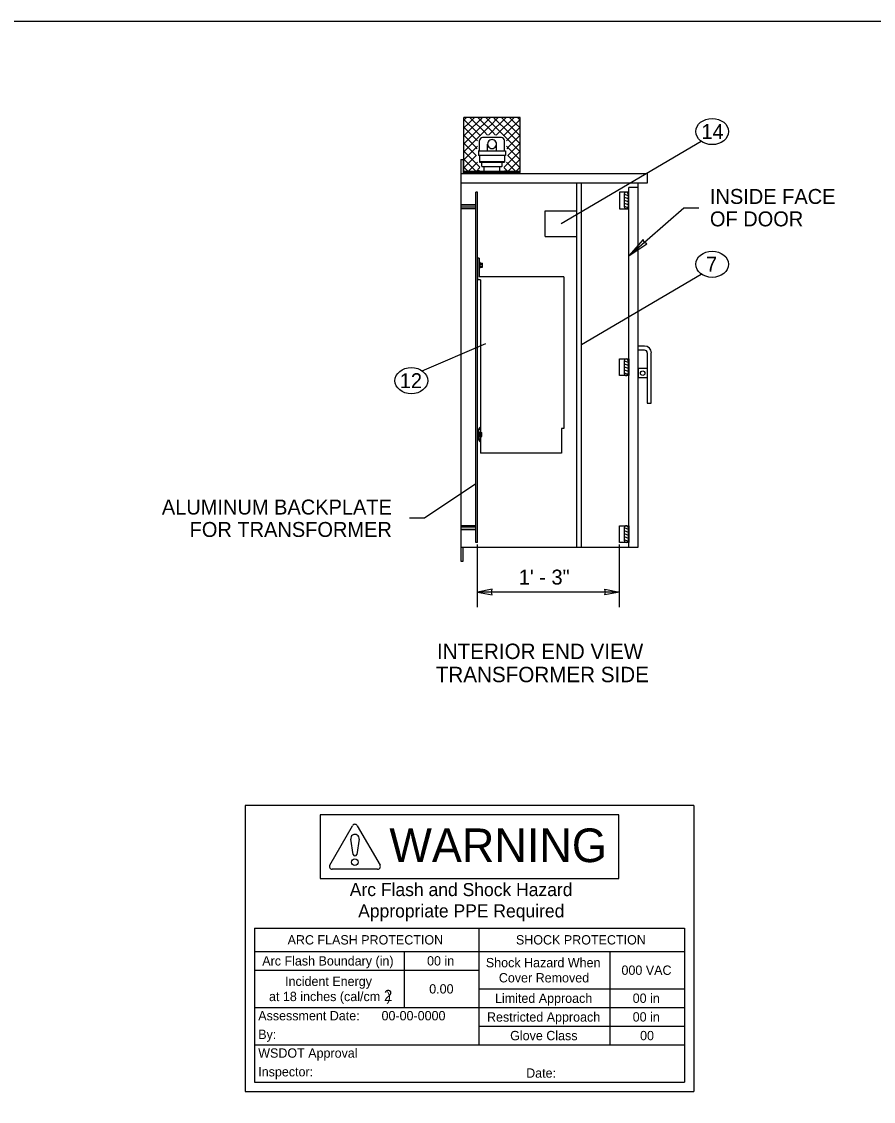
# Model space of a CAD drawing. Extents: x 99862 to 103680, y 99470 to 105076.
# Drawn here: x 100773 to 101684, y 103920 to 105076 of the extents above; entities that cross this region are included whole.
import ezdxf

# ---------------------------------------------------------------- set-up
doc = ezdxf.new("R2010")
doc.units = 0
for name, color, linetype in [('Level 1', 7, 'Continuous'), ('Level 15', 7, 'Continuous'), ('Level 20', 7, 'Continuous'), ('Level 35', 7, 'Continuous'), ('Level 40', 7, 'Continuous')]:
    doc.layers.add(name, color=color, linetype=linetype)

msp = doc.modelspace()

# ---------------------------------------------------------------- linework, layer by layer
at = {"layer": 'Level 1'}
for p, q in [((101246.5, 104915.2), (101246.5, 104972.9)), ((101306.5, 104972.9), (101246.5, 104972.9)), ((101246.5, 104970.7), (101246.7, 104970.5)), ((101246.7, 104970.5), (101246.5, 104970.3)), ((101246.5, 104962.2), (101246.7, 104962)), ((101246.7, 104970.5), (101249.1, 104972.9)), ((101250.9, 104966.2), (101246.7, 104970.5)), ((101246.7, 104962), (101250.9, 104966.2)), ((101255.2, 104970.5), (101250.9, 104966.2)), ((101250.9, 104966.2), (101255.2, 104962)), ((101252.7, 104972.9), (101255.2, 104970.5)), ((101257.6, 104972.9), (101255.2, 104970.5)), ((101255.2, 104970.5), (101259.4, 104966.2)), ((101259.4, 104966.2), (101255.2, 104962)), ((101259.4, 104966.2), (101263.7, 104970.5)), ((101263.7, 104962), (101259.4, 104966.2)), ((101263.7, 104970.5), (101261.2, 104972.9)), ((101266.1, 104972.9), (101263.7, 104970.5)), ((101263.7, 104970.5), (101268, 104966.2)), ((101268, 104966.2), (101263.7, 104962)), ((101268, 104966.2), (101272.2, 104970.5)), ((101272.2, 104962), (101268, 104966.2)), ((101272.2, 104970.5), (101269.8, 104972.9)), ((101274.7, 104972.9), (101272.2, 104970.5)), ((101272.2, 104970.5), (101276.5, 104966.2)), ((101276.5, 104966.2), (101272.2, 104962)), ((101276.5, 104966.2), (101280.7, 104970.5)), ((101280.7, 104962), (101276.5, 104966.2)), ((101280.7, 104970.5), (101278.3, 104972.9)), ((101283.2, 104972.9), (101280.7, 104970.5)), ((101280.7, 104970.5), (101285, 104966.2)), ((101285, 104966.2), (101280.7, 104962)), ((101285, 104966.2), (101289.2, 104970.5)), ((101289.2, 104962), (101285, 104966.2)), ((101289.2, 104970.5), (101286.8, 104972.9)), ((101291.7, 104972.9), (101289.2, 104970.5)), ((101289.2, 104970.5), (101293.5, 104966.2)), ((101293.5, 104966.2), (101289.2, 104962)), ((101293.5, 104966.2), (101297.7, 104970.5)), ((101297.7, 104962), (101293.5, 104966.2)), ((101295.3, 104972.9), (101297.7, 104970.5)), ((101297.7, 104970.5), (101300.2, 104972.9)), ((101297.7, 104970.5), (101302, 104966.2)), ((101302, 104966.2), (101297.7, 104962)), ((101302, 104966.2), (101306.2, 104970.5)), ((101306.2, 104962), (101302, 104966.2)), ((101306.2, 104970.5), (101303.8, 104972.9)), ((101306.5, 104970.7), (101306.2, 104970.5)), ((101306.2, 104970.5), (101306.5, 104970.3)), ((101306.5, 104962.2), (101306.2, 104962)), ((101306.5, 104915.2), (101306.5, 104972.9)), ((101246.7, 104962), (101246.5, 104961.8)), ((101246.5, 104953.7), (101246.7, 104953.5)), ((101246.7, 104953.5), (101246.5, 104953.2)), ((101250.9, 104957.7), (101246.7, 104962)), ((101246.7, 104953.5), (101250.9, 104957.7)), ((101250.9, 104949.2), (101246.7, 104953.5)), ((101255.2, 104962), (101250.9, 104957.7)), ((101250.9, 104957.7), (101255.2, 104953.5)), ((101255.2, 104953.5), (101250.9, 104949.2)), ((101255.2, 104962), (101259.4, 104957.7)), ((101259.4, 104957.7), (101255.2, 104953.5)), ((101255.2, 104953.5), (101259.4, 104949.2)), ((101259.4, 104957.7), (101263.7, 104962)), ((101263.7, 104953.5), (101259.4, 104957.7)), ((101259.4, 104949.2), (101263.7, 104953.5)), ((101263.7, 104962), (101268, 104957.7)), ((101268, 104957.7), (101263.7, 104953.5)), ((101263.7, 104953.5), (101263.9, 104953.3)), ((101286.5, 104951.4), (101266.4, 104951.4)), ((101268, 104957.7), (101272.2, 104962)), ((101271.8, 104953.8), (101268, 104957.7)), ((101272.2, 104962), (101276.5, 104957.7)), ((101276.5, 104957.7), (101272.6, 104953.8)), ((101276.5, 104957.7), (101280.7, 104962)), ((101280.3, 104953.8), (101276.5, 104957.7)), ((101280.7, 104962), (101285, 104957.7)), ((101285, 104957.7), (101281.1, 104953.8)), ((101285, 104957.7), (101289.2, 104962)), ((101289.2, 104953.5), (101285, 104957.7)), ((101289, 104953.3), (101289.2, 104953.5)), ((101289.2, 104962), (101293.5, 104957.7)), ((101293.5, 104957.7), (101289.2, 104953.5)), ((101289.2, 104953.5), (101293.5, 104949.2)), ((101293.5, 104957.7), (101297.7, 104962)), ((101297.7, 104953.5), (101293.5, 104957.7)), ((101293.5, 104949.2), (101297.7, 104953.5)), ((101297.7, 104962), (101302, 104957.7)), ((101302, 104957.7), (101297.7, 104953.5)), ((101297.7, 104953.5), (101302, 104949.2)), ((101302, 104957.7), (101306.2, 104962)), ((101306.2, 104953.5), (101302, 104957.7)), ((101302, 104949.2), (101306.2, 104953.5)), ((101306.2, 104962), (101306.5, 104961.8)), ((101306.5, 104953.7), (101306.2, 104953.5)), ((101306.2, 104953.5), (101306.5, 104953.2)), ((101246.5, 104945.2), (101246.7, 104945)), ((101246.7, 104945), (101246.5, 104944.7)), ((101246.7, 104945), (101250.9, 104949.2)), ((101250.9, 104940.7), (101246.7, 104945)), ((101246.7, 104936.5), (101250.9, 104940.7)), ((101250.9, 104949.2), (101255.2, 104945)), ((101255.2, 104945), (101250.9, 104940.7)), ((101250.9, 104940.7), (101255.2, 104936.5)), ((101259.4, 104949.2), (101255.2, 104945)), ((101255.2, 104945), (101259.4, 104940.7)), ((101259.4, 104940.7), (101255.2, 104936.5)), ((101260.8, 104947.8), (101259.4, 104949.2)), ((101259.4, 104940.7), (101260.8, 104942.1)), ((101260.7, 104939.4), (101259.4, 104940.7)), ((101263.2, 104937), (101263.2, 104948.2)), ((101271.6, 104937), (101271.6, 104944.4)), ((101281.3, 104937), (101281.3, 104944.4)), ((101289.7, 104937), (101289.7, 104948.2)), ((101293.5, 104949.2), (101292.1, 104947.8)), ((101292.1, 104942.1), (101293.5, 104940.7)), ((101293.5, 104940.7), (101292.2, 104939.4)), ((101297.7, 104945), (101293.5, 104949.2)), ((101293.5, 104940.7), (101297.7, 104945)), ((101297.7, 104936.5), (101293.5, 104940.7)), ((101302, 104949.2), (101297.7, 104945)), ((101297.7, 104945), (101302, 104940.7)), ((101302, 104940.7), (101297.7, 104936.5)), ((101306.2, 104945), (101302, 104949.2)), ((101302, 104940.7), (101306.2, 104945)), ((101306.2, 104936.5), (101302, 104940.7)), ((101306.5, 104945.2), (101306.2, 104945)), ((101306.2, 104945), (101306.5, 104944.7)), ((101246.5, 104936.7), (101246.7, 104936.5)), ((101246.7, 104936.5), (101246.5, 104936.2)), ((101246.5, 104928.2), (101246.7, 104927.9)), ((101246.7, 104927.9), (101246.5, 104927.7)), ((101250.9, 104932.2), (101246.7, 104936.5)), ((101246.7, 104927.9), (101250.9, 104932.2)), ((101250.9, 104923.7), (101246.7, 104927.9)), ((101255.2, 104936.5), (101250.9, 104932.2)), ((101250.9, 104932.2), (101255.2, 104927.9)), ((101255.2, 104927.9), (101250.9, 104923.7)), ((101255.2, 104936.5), (101259.4, 104932.2)), ((101259.4, 104932.2), (101255.2, 104927.9)), ((101255.2, 104927.9), (101259.4, 104923.7)), ((101259.4, 104932.2), (101259.6, 104932.4)), ((101259.6, 104932), (101259.4, 104932.2)), ((101263.2, 104937), (101262, 104937)), ((101262, 104937), (101262, 104932.2)), ((101290.9, 104932.2), (101262, 104932.2)), ((101263.2, 104937), (101289.7, 104937)), ((101263.2, 104932.2), (101263.2, 104925)), ((101289.7, 104937), (101290.9, 104937)), ((101289.7, 104932.2), (101289.7, 104925)), ((101290.9, 104937), (101290.9, 104932.2)), ((101293.3, 104932.4), (101293.5, 104932.2)), ((101293.5, 104932.2), (101293.3, 104932)), ((101293.5, 104932.2), (101297.7, 104936.5)), ((101297.7, 104927.9), (101293.5, 104932.2)), ((101293.5, 104923.7), (101297.7, 104927.9)), ((101297.7, 104936.5), (101302, 104932.2)), ((101302, 104932.2), (101297.7, 104927.9)), ((101297.7, 104927.9), (101302, 104923.7)), ((101302, 104932.2), (101306.2, 104936.5)), ((101306.2, 104927.9), (101302, 104932.2)), ((101302, 104923.7), (101306.2, 104927.9)), ((101306.5, 104936.7), (101306.2, 104936.5)), ((101306.2, 104936.5), (101306.5, 104936.2)), ((101306.5, 104928.2), (101306.2, 104927.9)), ((101306.2, 104927.9), (101306.5, 104927.7)), ((101246.5, 104919.7), (101246.7, 104919.4)), ((101246.7, 104919.4), (101246.5, 104919.2)), ((101246.7, 104919.4), (101250.9, 104923.7)), ((101250.9, 104915.2), (101246.7, 104919.4)), ((101250.9, 104923.7), (101255.2, 104919.4)), ((101255.2, 104919.4), (101250.9, 104915.2)), ((101259.4, 104923.7), (101255.2, 104919.4)), ((101255.2, 104919.4), (101259.4, 104915.2)), ((101259.4, 104923.7), (101260.8, 104925.1)), ((101263.4, 104919.7), (101259.4, 104923.7)), ((101259.4, 104915.2), (101263.6, 104919.3)), ((101263.2, 104925.6), (101289.7, 104925.6)), ((101263.2, 104925), (101289.7, 104925)), ((101265.6, 104920.8), (101265.6, 104925)), ((101266.2, 104920.2), (101286.7, 104920.2)), ((101268, 104915.3), (101268, 104920.2)), ((101284.9, 104915.3), (101284.9, 104920.2)), ((101287.3, 104920.8), (101287.3, 104925)), ((101289.3, 104919.3), (101293.5, 104915.2)), ((101293.5, 104923.7), (101289.5, 104919.7)), ((101292.1, 104925.1), (101293.5, 104923.7)), ((101297.7, 104919.4), (101293.5, 104923.7)), ((101293.5, 104915.2), (101297.7, 104919.4)), ((101302, 104923.7), (101297.7, 104919.4)), ((101297.7, 104919.4), (101302, 104915.2)), ((101306.2, 104919.4), (101302, 104923.7)), ((101302, 104915.2), (101306.2, 104919.4)), ((101306.5, 104919.7), (101306.2, 104919.4)), ((101306.2, 104919.4), (101306.5, 104919.2)), ((101306.5, 104915.2), (101246.5, 104915.2)), ((101246.5, 104914.1), (101246.5, 104915.1)), ((101306.5, 104915.1), (101246.5, 104915.1)), ((101306.5, 104914.1), (101246.5, 104914.1)), ((101270.4, 104912.9), (101282.5, 104912.9)), ((101306.5, 104914.1), (101306.5, 104915.1)), ((101367.2, 104512.9), (101367.2, 104902.9)), ((101372.2, 104512.9), (101372.2, 104902.9)), ((101423, 104875.1), (101423, 104892.9)), ((101418, 104890.9), (101418, 104877.1)), ((101418, 104890.9), (101422, 104889.3)), ((101418, 104887.7), (101422, 104886.1)), ((101418, 104884.4), (101422, 104882.9)), ((101422, 104890.9), (101422, 104877.1)), ((101333.4, 104845.5), (101333.4, 104873)), ((101333.4, 104873), (101367.2, 104873)), ((101418, 104881.2), (101422, 104879.7)), ((101418, 104878), (101421.9, 104876.5)), ((101333.4, 104845.5), (101367.2, 104845.5)), ((101260.9, 104822.3), (101260.9, 104798.9)), ((101262.6, 104822.3), (101260.9, 104822.3)), ((101262.6, 104822.3), (101262.6, 104802.3)), ((101353.4, 104802.3), (101262.6, 104802.3)), ((101353.4, 104802.3), (101353.4, 104639.9)), ((101264.3, 104798.9), (101260.9, 104798.9)), ((101264.3, 104798.9), (101264.3, 104613.5)), ((101439.7, 104728.2), (101433, 104728.2)), ((101439.7, 104723.7), (101433, 104723.7)), ((101442.5, 104720.9), (101442.5, 104666.9)), ((101446.9, 104666.9), (101446.9, 104720.9)), ((101418, 104712.3), (101418, 104698.6)), ((101418, 104712.3), (101422, 104710.8)), ((101418, 104709.1), (101422, 104707.6)), ((101422, 104712.3), (101422, 104698.6)), ((101423, 104714.3), (101423, 104696.6)), ((101418, 104705.9), (101422, 104704.4)), ((101418, 104702.7), (101422, 104701.1)), ((101418, 104699.5), (101421.9, 104698)), ((101442.5, 104704.1), (101433, 104704.1)), ((101433, 104704.1), (101433, 104694.1)), ((101442.5, 104694.1), (101433, 104694.1)), ((101442.5, 104666.9), (101446.9, 104666.9)), ((101260.9, 104638.2), (101264.3, 104641.6)), ((101262, 104637.7), (101264.3, 104640)), ((101353.4, 104639.9), (101350.9, 104639.9)), ((101350.9, 104639.9), (101350.9, 104613.5)), ((101260.9, 104628.8), (101260.9, 104638.2)), ((101260.9, 104628.8), (101264.3, 104625.4)), ((101262, 104629.4), (101262, 104637.7)), ((101262, 104629.4), (101264.3, 104627.1)), ((101350.9, 104613.5), (101264.3, 104613.5)), ((101423, 104535.8), (101423, 104518)), ((101418, 104533.8), (101418, 104520)), ((101418, 104533.8), (101422, 104532.2)), ((101418, 104530.6), (101422, 104529)), ((101418, 104527.4), (101422, 104525.8)), ((101418, 104524.1), (101422, 104522.6)), ((101422, 104533.8), (101422, 104520)), ((101418, 104520.9), (101421.9, 104519.4))]:
    msp.add_line(p, q, dxfattribs=at)
msp.add_lwpolyline([(99862, 102999.5), (103151, 102999.5), (103151, 105075.5), (99862, 105075.5)], close=True, dxfattribs=at)
for points in [[(101423, 104892.9), (101413, 104892.9), (101413, 104875.1), (101423, 104875.1)], [(101423, 104696.6), (101413, 104696.6), (101413, 104714.3), (101423, 104714.3)], [(101423, 104518), (101413, 104518), (101413, 104535.8), (101423, 104535.8)]]:
    msp.add_lwpolyline(points, dxfattribs=at)
msp.add_circle((101437.7, 104699.1), 2.37, dxfattribs=at)
for centre, radius, start, end in [((101266.4, 104948.2), 3.21, 90, 180), ((101286.5, 104948.2), 3.21, 0, 90), ((101276.5, 104944.4), 4.81, 359.9997, 180), ((101276.5, 104944.4), 4.81, 180, 0.0003), ((101266.2, 104920.8), 0.602, 180, 270), ((101286.7, 104920.8), 0.602, 270, 0), ((101270.4, 104915.3), 2.41, 180, 270), ((101282.5, 104915.3), 2.41, 270, 0), ((101420, 104890.9), 2, 90, 180), ((101420, 104890.9), 2, 0, 90), ((101420, 104877.1), 2, 180, 270), ((101420, 104877.1), 2, 270, 0), ((101439.7, 104720.9), 7.25, 0, 90), ((101439.7, 104720.9), 2.82, 0, 90), ((101420, 104712.3), 2, 90, 180), ((101420, 104712.3), 2, 0, 90), ((101420, 104698.6), 2, 180, 270), ((101420, 104698.6), 2, 270, 0), ((101420, 104533.8), 2, 90, 180), ((101420, 104533.8), 2, 0, 90), ((101420, 104520), 2, 180, 270), ((101420, 104520), 2, 270, 0)]:
    msp.add_arc(centre, radius, start, end, dxfattribs=at)
at = {"layer": 'Level 15'}
for p, q in [((101350.5, 104859.2), (101500.3, 104947.4)), ((101243, 104902.9), (101433, 104902.9)), ((101423, 104512.9), (101423, 104897.9)), ((101433, 104897.9), (101423, 104897.9)), ((101423, 104824.9), (101481.6, 104876.3)), ((101481.6, 104876.3), (101497.6, 104876.3)), ((101372.2, 104729.8), (101500.3, 104805.2)), ((101201.8, 104701.6), (101269.7, 104731)), ((101259.2, 104580.8), (101204.3, 104543.8)), ((101204.3, 104543.8), (101188.3, 104543.8)), ((101245.5, 104497.9), (101245.5, 104512.9)), ((101260.9, 104448.8), (101260.9, 104515.8)), ((101413, 104448.8), (101413, 104515.8)), ((101243, 104497.9), (101245.5, 104497.9)), ((101413, 104464.8), (101260.9, 104464.8))]:
    msp.add_line(p, q, dxfattribs=at)
for points in [[(101423, 104824.9), (101442.1, 104837.7), (101439.3, 104839.2), (101438.2, 104842.2)], [(101260.9, 104464.8), (101276.6, 104461.7), (101275.9, 104464.8), (101276.6, 104467.9)], [(101413, 104464.8), (101397.2, 104461.7), (101398, 104464.8), (101397.2, 104467.9)]]:
    msp.add_lwpolyline(points, close=True, dxfattribs=at)
at = {"layer": 'Level 20'}
for centre in [(101512, 104957.8), (101512, 104815.7), (101190.2, 104691.1)]:
    msp.add_ellipse(centre, major_axis=(-17.5, 0), ratio=0.8, dxfattribs=at)
at = {"layer": 'Level 35'}
for p, q in [((101012.5, 104236.2), (101012.5, 103930)), ((101492.5, 104236.2), (101012.5, 104236.2)), ((101492.5, 104236.2), (101492.5, 103930)), ((101127.8, 104184), (101125.3, 104200.1)), ((101134.2, 104200.1), (101131.7, 104184)), ((101022.5, 104105), (101022.5, 103940)), ((101022.5, 104105), (101482.5, 104105)), ((101262.5, 104105), (101262.5, 103980)), ((101482.5, 104105), (101482.5, 103940)), ((101022.5, 104080), (101482.5, 104080)), ((101182.5, 104080), (101182.5, 104020)), ((101402.5, 104080), (101402.5, 103980)), ((101022.5, 104060), (101262.5, 104060)), ((101262.5, 104040), (101482.5, 104040)), ((101022.5, 104020), (101262.5, 104020)), ((101262.5, 104020), (101482.5, 104020)), ((101262.5, 104000), (101482.5, 104000)), ((101022.5, 103980), (101262.5, 103980)), ((101262.5, 103980), (101482.5, 103980)), ((101022.5, 103940), (101482.5, 103940)), ((101012.5, 103930), (101492.5, 103930))]:
    msp.add_line(p, q, dxfattribs=at)
msp.add_lwpolyline([(101092.6, 104158.1), (101412.3, 104158.1), (101412.3, 104226.2), (101092.6, 104226.2)], close=True, dxfattribs=at)
for points in [[(101102.9, 104172.6), (101127.2, 104214.7)], [(101132.4, 104214.7), (101156.7, 104172.6)], [(101154.1, 104168.1), (101105.5, 104168.1)]]:
    msp.add_lwpolyline(points, dxfattribs=at)
msp.add_circle((101129.7, 104175.7), 3.58, dxfattribs=at)
for centre, radius, start, end in [((101129.8, 104213.2), 3, 30, 150), ((101129.8, 104200.8), 4.54, 351.09, 188.91), ((101129.8, 104184.3), 1.99, 188.91, 351.09), ((101105.5, 104171.1), 3, 150, 270), ((101154.1, 104171.1), 3, 270, 30)]:
    msp.add_arc(centre, radius, start, end, dxfattribs=at)
at = {"layer": 'Level 40'}
for p, q in [((101243, 104927.9), (101243, 104497.9)), ((101243, 104927.9), (101245.5, 104927.9)), ((101245.5, 104927.9), (101245.5, 104912.9)), ((101243, 104912.9), (101443, 104912.9)), ((101443, 104902.9), (101443, 104912.9)), ((101259.2, 104518), (101259.2, 104892.9)), ((101260.9, 104892.9), (101259.2, 104892.9)), ((101260.9, 104518), (101260.9, 104892.9)), ((101433, 104512.9), (101433, 104902.9)), ((101433, 104902.9), (101443, 104902.9)), ((101259.2, 104879.5), (101243, 104879.5)), ((101259.2, 104879), (101243, 104879)), ((101259.2, 104876.8), (101243, 104876.8)), ((101259.2, 104875.1), (101243, 104875.1)), ((101262.6, 104817.8), (101263.8, 104817.8)), ((101263.8, 104811.9), (101263.8, 104817.8)), ((101263.8, 104817), (101266.3, 104817)), ((101263.8, 104815.3), (101266.3, 104815.3)), ((101263.8, 104813.2), (101266.3, 104813.2)), ((101263.8, 104812.7), (101266.3, 104812.7)), ((101266.3, 104812.7), (101266.3, 104817)), ((101262.6, 104811.9), (101263.8, 104811.9)), ((101262, 104636.5), (101263.2, 104636.5)), ((101262, 104630.6), (101263.2, 104630.6)), ((101263.2, 104630.6), (101263.2, 104636.5)), ((101263.2, 104635.7), (101265.7, 104635.7)), ((101263.2, 104634), (101265.7, 104634)), ((101263.2, 104631.9), (101265.7, 104631.9)), ((101263.2, 104631.4), (101265.7, 104631.4)), ((101265.7, 104631.4), (101265.7, 104635.7)), ((101259.2, 104535.7), (101243, 104535.7)), ((101259.2, 104534.1), (101243, 104534.1)), ((101259.2, 104531.9), (101243, 104531.9)), ((101259.2, 104531.4), (101243, 104531.4)), ((101243, 104512.9), (101433, 104512.9)), ((101260.9, 104518), (101259.2, 104518))]:
    msp.add_line(p, q, dxfattribs=at)
for points in [[(101263.3, 104913.3), (101263.3, 104913.2), (101260.7, 104913.2), (101260.7, 104913.3)], [(101263.4, 104913.2), (101263.4, 104912.9), (101260.7, 104912.9), (101260.7, 104913.2)], [(101263, 104915.1), (101263, 104915.9), (101261, 104915.9), (101261, 104915.1)], [(101263, 104913.3), (101263, 104914.1), (101261, 104914.1), (101261, 104913.3)], [(101289.6, 104913.3), (101289.6, 104913.2), (101292.2, 104913.2), (101292.2, 104913.3)], [(101289.6, 104913.2), (101289.6, 104912.9), (101292.2, 104912.9), (101292.2, 104913.2)], [(101289.9, 104915.1), (101289.9, 104915.9), (101291.9, 104915.9), (101291.9, 104915.1)], [(101289.9, 104913.3), (101289.9, 104914.1), (101291.9, 104914.1), (101291.9, 104913.3)]]:
    msp.add_lwpolyline(points, close=True, dxfattribs=at)

# ---------------------------------------------------------------- texts
at = {"layer": 'Level 20'}
for s, height, p in [('14', 16, (101500.5, 104949.8)), ('INSIDE FACE', 16, (101509.6, 104880.3)), ('OF DOOR', 16, (101509.6, 104856.3)), ('7', 16, (101505.4, 104807.7)), ('12', 16, (101177.8, 104683.1)), ('ALUMINUM BACKPLATE', 16, (100923.3, 104547.8)), ('FOR TRANSFORMER', 16, (100953, 104523.8)), ('INTERIOR END VIEW', 16.5, (101217.6, 104393.1)), (' TRANSFORMER SIDE', 16.5, (101210.2, 104368.3))]:
    msp.add_text(s, height=height, dxfattribs=at).set_placement(p)
msp.add_text('1\' - 3"', height=16, rotation=360, dxfattribs=at).set_placement((101305.1, 104472.8))
at = {"layer": 'Level 35'}
for s, height, p in [('WARNING', 36, (101166.7, 104175.7)), ('Arc Flash and Shock Hazard', 14, (101124.3, 104139.3)), ('Appropriate PPE Required', 14, (101133.3, 104116.5)), ('ARC FLASH PROTECTION', 10, (101057.8, 104087.5)), ('SHOCK PROTECTION', 10, (101302.1, 104087.5)), ('Arc Flash Boundary (in)', 10, (101030.7, 104065)), ('00 in', 10, (101207, 104065)), ('Shock Hazard When', 10, (101269.9, 104063.1)), ('000 VAC', 10, (101415, 104055)), ('Incident Energy', 10, (101055.1, 104043.1)), ('Cover Removed', 10, (101283.8, 104046.9)), ('at 18 inches (cal/cm', 10, (101037.9, 104026.9)), ('2', 12, (101160.9, 104026.9)), (')', 10, (101163.7, 104026.9)), ('0.00', 10, (101209.3, 104035)), ('Limited Approach', 10, (101279.7, 104025)), ('00 in', 10, (101427, 104025)), ('Assessment Date:', 10, (101026.4, 104006.3)), ('00-00-0000', 10, (101158.3, 104006.3)), ('Restricted Approach', 10, (101271.1, 104004.9)), ('00 in', 10, (101427, 104005)), ('By:', 10, (101026.4, 103986.3)), ('Glove Class', 10, (101295.9, 103985)), ('00', 10, (101434.9, 103985)), ('WSDOT Approval', 10, (101026.4, 103966.3)), ('Inspector:', 10, (101026.4, 103946.3)), ('Date:', 10, (101313, 103944.9))]:
    msp.add_text(s, height=height, dxfattribs=at).set_placement(p)

doc.saveas('drawing.dxf')
